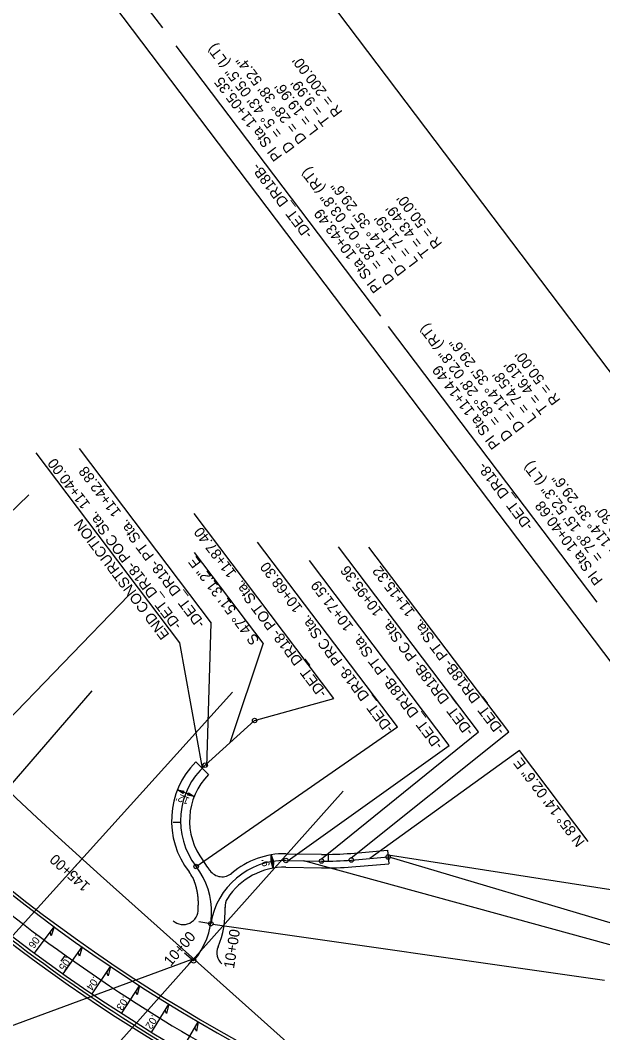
# Model space of a CAD drawing. Extents: x 473658 to 481584, y 489119 to 506230.
# Drawn here: x 476657 to 477047, y 500561 to 501237 of the extents above; entities that cross this region are included whole.
import ezdxf

# ---------------------------------------------------------------- set-up
doc = ezdxf.new("R2010")
doc.units = 0
for name, color, linetype in [('Exist Horizontal Alignment', 7, 'Continuous'), ('Prop Dimension', 7, 'Continuous'), ('Prop EOT', 7, 'Continuous'), ('Prop Grid Mask', 7, 'Continuous'), ('Prop Guardrail', 7, 'Continuous'), ('Prop Horizontal Alignment', 7, 'Continuous'), ('Prop Horizontal Alignment Curve and Spiral Data', 7, 'Continuous'), ('Prop Horizontal Alignment Direction Label', 7, 'Continuous'), ('Prop Horizontal Alignment Station Label', 7, 'Continuous'), ('Prop Horizontal Alignment Tick Label', 7, 'Continuous'), ('Prop Horizontal Alignment Tick Large', 7, 'Continuous'), ('Prop Horizontal Alignment Tick Small', 7, 'Continuous'), ('Prop Paved Shoulder', 7, 'Continuous'), ('Prop Superelevation  Arrow CELL', 7, 'Continuous'), ('Prop Superelevation Label', 7, 'Continuous'), ('Scratch_Level_6', 7, 'Continuous'), ('Sheet Plan And Profile CELL', 7, 'Continuous')]:
    doc.layers.add(name, color=color, linetype=linetype)

msp = doc.modelspace()

# ---------------------------------------------------------------- linework, layer by layer
at = {"layer": 'Exist Horizontal Alignment'}
for points in [[(476766.35, 500720.84), (476762.45, 500723.22), (476766.95, 500722.29), (476766.12, 500721.76)], [(476769.71, 500721.17), (476773.61, 500718.8), (476769.11, 500719.72), (476769.94, 500720.25)], [(476824.98, 500675.22), (476824.99, 500679.79), (476826.53, 500675.46), (476825.65, 500675.89)], [(476826.5, 500675.48), (476826.49, 500670.92), (476824.95, 500675.24), (476825.83, 500674.81)]]:
    msp.add_lwpolyline(points, close=True, dxfattribs=at)
at = {"layer": 'Prop Dimension'}
for p, q in [((476773.61, 500718.8), (476762.45, 500723.22)), ((476826.49, 500670.92), (476824.99, 500679.79))]:
    msp.add_line(p, q, dxfattribs=at)
at = {"layer": 'Prop EOT'}
for p, q in [((476774.61, 500741.87), (476783.16, 500733.45)), ((476834.99, 500680.55), (476858.76, 500680.15)), ((476878.25, 500680.8), (476902.84, 500682.85)), ((476902.84, 500682.85), (476903.59, 500673.88)), ((476834.84, 500671.55), (476858.61, 500671.15)), ((476879, 500671.83), (476903.59, 500673.88))]:
    msp.add_line(p, q, dxfattribs=at)
for centre, radius, start, end in [((477327.21, 501507.62), 1089, 218.24077, 241.8577), ((477327.21, 501507.62), 1111, 218.24077, 241.40091), ((476814.51, 500702.58), 56, 135.44556, 217.60879), ((476814.51, 500702.58), 44, 135.44556, 217.60879), ((476834.08, 500626.05), 54.5, 89.04778, 130.38858), ((476862.01, 500875.62), 195.5, 269.04778, 274.76596), ((476735.29, 500641.56), 56, 31.76656, 37.60879), ((476834.08, 500626.05), 45.5, 89.04778, 147.34296), ((476862.01, 500875.62), 204.5, 269.04778, 274.76596), ((476735.29, 500641.56), 44, 31.76656, 37.60879), ((476792.29, 500675.18), 10, 215.7109, 310.38858), ((476804.19, 500645.21), 10, 147.34296, 183.03589), ((476766.25, 500643.24), 10, 228.41849, 3.11379), ((476735.29, 500641.56), 59, 336.83919, 3.11867), ((476798.73, 500614.42), 10, 156.83919, 228.41849)]:
    msp.add_arc(centre, radius, start, end, dxfattribs=at)
msp.add_open_spline([(476784.35, 500669.1), (476784.32, 500669.13), (476784.3, 500669.17), (476784.27, 500669.2), (476784.2, 500669.31), (476784.12, 500669.41), (476784.05, 500669.51), (476783.97, 500669.62), (476783.9, 500669.72), (476783.82, 500669.82), (476783.75, 500669.92), (476783.67, 500670.03), (476783.6, 500670.13), (476783.52, 500670.23), (476783.44, 500670.33), (476783.37, 500670.43), (476783.21, 500670.63), (476783.06, 500670.84), (476782.9, 500671.04)], degree=3, dxfattribs=at)
msp.add_spline([(476776.23, 500643.78), (476776.26, 500644.06), (476776.28, 500644.34), (476776.3, 500644.62), (476776.32, 500644.9), (476776.33, 500645.18), (476776.35, 500645.46), (476776.36, 500645.74), (476776.37, 500646.03), (476776.38, 500646.31), (476776.39, 500646.59), (476776.39, 500646.87), (476776.4, 500647.16), (476776.4, 500647.44), (476776.4, 500647.72), (476776.4, 500648.01), (476776.39, 500648.29), (476776.39, 500648.58), (476776.38, 500648.86), (476776.37, 500649.15), (476776.35, 500649.43), (476776.34, 500649.72), (476776.32, 500650), (476776.3, 500650.29), (476776.28, 500650.57), (476776.26, 500650.86), (476776.24, 500651.14), (476776.21, 500651.43), (476776.18, 500651.72), (476776.15, 500652), (476776.12, 500652.29), (476776.09, 500652.58), (476776.05, 500652.86), (476776.01, 500653.15), (476775.97, 500653.43), (476775.93, 500653.72), (476775.88, 500654.01), (476775.84, 500654.29), (476775.79, 500654.58), (476775.74, 500654.87), (476775.69, 500655.15), (476775.63, 500655.44), (476775.58, 500655.72), (476775.52, 500656.01), (476775.46, 500656.29), (476775.39, 500656.58), (476775.33, 500656.86), (476775.26, 500657.15), (476775.19, 500657.43), (476775.12, 500657.72), (476775.05, 500658), (476774.98, 500658.29), (476774.9, 500658.57), (476774.82, 500658.85), (476774.74, 500659.14), (476774.66, 500659.42), (476774.57, 500659.7), (476774.49, 500659.99), (476774.4, 500660.27), (476774.31, 500660.55), (476774.21, 500660.83), (476774.12, 500661.11), (476774.02, 500661.39), (476773.92, 500661.67), (476773.82, 500661.95), (476773.72, 500662.23), (476773.61, 500662.51), (476773.51, 500662.79), (476773.4, 500663.06), (476773.29, 500663.34), (476773.17, 500663.62), (476773.06, 500663.89), (476772.94, 500664.17), (476772.7, 500664.72)], degree=3, dxfattribs=at)
at = {"layer": 'Prop Grid Mask'}
msp.add_lwpolyline([(477240.37, 500559.92), (476603.51, 501401.29), (476696.24, 501471.48), (477333.1, 500630.11)], close=True, dxfattribs=at)
at = {"layer": 'Prop Guardrail'}
msp.add_arc((477327.21, 501507.62), 1115, 218.24077, 239.00479, dxfattribs=at)
at = {"layer": 'Prop Horizontal Alignment'}
for p, q in [((476780.96, 500739.66), (476813.97, 500769.53)), ((476878.62, 500676.32), (476903.24, 500678.37)), ((476834.91, 500676.05), (476858.68, 500675.65)), ((477070.66, 500345.01), (476711.11, 500665.95))]:
    msp.add_line(p, q, dxfattribs=at)
for centre, radius, start, end in [((478615.62, 502799.59), 2860, 203.81642, 228.24762), ((477327.21, 501507.62), 1100, 218.24077, 241.8577), ((476814.51, 500702.58), 50, 132.14135, 217.60879), ((476735.29, 500641.56), 50, 319.34469, 37.60879), ((476834.08, 500626.05), 50, 89.04778, 171.08217), ((476862.01, 500875.62), 200, 269.04778, 274.76596)]:
    msp.add_arc(centre, radius, start, end, dxfattribs=at)
at = {"layer": 'Prop Horizontal Alignment Curve and Spiral Data'}
for p, q in [((476752.6, 501231.95), (476622.16, 501404.27)), ((476898.3, 501039.46), (476761.57, 501220.09)), ((477042.84, 500848.51), (476903.48, 501032.62))]:
    msp.add_line(p, q, dxfattribs=at)
at = {"layer": 'Prop Horizontal Alignment Station Label'}
for p, q in [((476667.82, 500948.24), (476763.86, 500821.36)), ((476696.65, 500951.06), (476784.89, 500834.49)), ((476866.97, 500784.27), (476773.53, 500907.7)), ((476909.36, 500765.2), (476815.93, 500888.64)), ((476819.78, 500821.18), (476773.92, 500881.77)), ((476963.51, 500761.95), (476870.07, 500885.38)), ((476983.76, 500761.85), (476890.33, 500885.29)), ((476944.01, 500752.85), (476850.57, 500876.28)), ((476781.97, 500738.54), (476784.89, 500834.49)), ((476763.86, 500821.36), (476778.88, 500737.66)), ((476819.78, 500821.18), (476797.47, 500754.59)), ((476813.97, 500769.53), (476866.97, 500784.27)), ((476774.9, 500672.07), (476909.36, 500765.2)), ((476858.71, 500677.15), (476963.51, 500761.95)), ((476878.5, 500677.81), (476983.76, 500761.85)), ((476836.41, 500676.02), (476944.01, 500752.85)), ((476991.06, 500749.39), (476890.93, 500677.34)), ((477036.92, 500688.8), (476991.06, 500749.39)), ((476903.12, 500679.86), (477119.45, 500646.11)), ((477089.88, 500622.89), (476903.22, 500678.37)), ((477068.24, 500615), (476846.8, 500675.85)), ((476786.17, 500633.57), (477047.84, 500596.21)), ((476772.09, 500609.96), (476453.22, 500492.62))]:
    msp.add_line(p, q, dxfattribs=at)
for centre in [(476813.97, 500769.53), (476780.96, 500739.66), (476834.91, 500676.05), (476834.91, 500676.05), (476858.68, 500675.65), (476858.68, 500675.65), (476878.62, 500676.32), (476878.62, 500676.32), (476903.24, 500678.37), (476903.24, 500678.37), (476774.9, 500672.07), (476784.69, 500633.8), (476784.69, 500633.8), (476773.22, 500608.98)]:
    msp.add_circle(centre, 1.5, dxfattribs=at)
at = {"layer": 'Prop Horizontal Alignment Tick Large'}
for p, q in [((476698.65, 500677.13), (476693.29, 500671.2)), ((476784.69, 500633.8), (476776.78, 500635.04)), ((476784.69, 500633.8), (476776.78, 500635.04)), ((476773.22, 500608.98), (476767.15, 500614.19))]:
    msp.add_line(p, q, dxfattribs=at)
at = {"layer": 'Prop Horizontal Alignment Tick Small'}
for p, q in [((476764.52, 500701.46), (476759.52, 500701.35)), ((476863.32, 500675.63), (476863.29, 500680.63)), ((476863.32, 500675.63), (476863.29, 500680.63)), ((476687.43, 500612.82), (476684.52, 500608.75)), ((476773.22, 500610.51), (476769.89, 500606.78))]:
    msp.add_line(p, q, dxfattribs=at)
at = {"layer": 'Prop Paved Shoulder'}
for radius, end in [(1087, 241.8577), (1113, 241.70868)]:
    msp.add_arc((477327.21, 501507.62), radius, 218.24077, end, dxfattribs=at)
at = {"layer": 'Prop Superelevation  Arrow CELL'}
for points in [[(476680.02, 500631.8), (476678.06, 500625.79), (476677.27, 500628.08)], [(476698.74, 500618.28), (476696.91, 500612.22), (476696.07, 500614.5)], [(476717.74, 500605.15), (476716.04, 500599.06), (476715.15, 500601.31)], [(476737.02, 500592.42), (476735.44, 500586.3), (476734.51, 500588.54)], [(476756.56, 500580.11), (476755.12, 500573.96), (476754.13, 500576.17)], [(476776.36, 500568.22), (476775.05, 500562.03), (476774.02, 500564.23)]]:
    msp.add_lwpolyline(points, close=True, dxfattribs=at)
at = {"layer": 'Prop Superelevation Label'}
for p, q in [((476666.94, 500614.11), (476680.02, 500631.8)), ((476686.04, 500600.31), (476698.74, 500618.28)), ((476705.43, 500586.91), (476717.74, 500605.15)), ((476725.09, 500573.94), (476737.02, 500592.42)), ((476745.2, 500561.65), (476756.56, 500580.11)), ((476765.23, 500549.24), (476776.36, 500568.22))]:
    msp.add_line(p, q, dxfattribs=at)
at = {"layer": 'Scratch_Level_6'}
msp.add_line((476509.12, 500562.51), (476705.47, 500789.34), dxfattribs=at)
at = {"layer": 'Sheet Plan And Profile CELL'}
for p, q in [((476446.96, 500712.24), (476663.1, 500920.29)), ((476521.25, 500637.71), (476729.99, 500853.18)), ((476598.11, 500565.82), (476799.19, 500788.45)), ((476673.33, 500498.6), (476873.11, 500722.41))]:
    msp.add_line(p, q, dxfattribs=at)

# ---------------------------------------------------------------- texts
at = {"layer": 'Prop Dimension'}
for s, rotation, p in [("12'", 158.37706, (476770.86, 500717.73)), ("9'", 99.60568, (476824.2, 500672.44))]:
    msp.add_text(s, height=5, rotation=rotation, dxfattribs=at).set_placement(p)
at = {"layer": 'Prop Horizontal Alignment Curve and Spiral Data'}
for s, p in [('= 5%%d 43\' 05.5" (LT)', (476833.11, 501161.81)), ('D = 28%%d 38\' 52.4"', (476849.08, 501157.78)), ("R = 200.00'", (476873, 501175.88)), ('PI Sta 11+05.35', (476832.72, 501146.24)), ("L = 19.96'", (476857.05, 501163.81)), ("T = 9.99'", (476865.02, 501169.85)), ('D', (476841.1, 501151.74)), ('= 82%%d 02\' 03.8" (RT)', (476899.72, 501073.81)), ('D = 114%%d 35\' 29.6"', (476915.69, 501069.78)), ("R = 50.00'", (476939.61, 501087.88)), ('PI Sta 10+43.49', (476899.33, 501058.24)), ("T = 43.49'", (476931.63, 501081.85)), ("L = 71.59'", (476923.66, 501075.81)), ('D', (476907.71, 501063.74)), ('= 85%%d 28\' 02.8" (RT)', (476978.77, 500969.38)), ('D = 114%%d 35\' 29.6"', (476994.73, 500965.35)), ("R = 50.00'", (477018.65, 500983.45)), ("T = 46.19'", (477010.68, 500977.42)), ('PI Sta 11+14.49', (476978.38, 500953.81)), ("L = 74.58'", (477002.71, 500971.38)), ('D', (476986.76, 500959.31)), ('= 78%%d 15\' 52.3" (LT)', (477047.39, 500878.72)), ('D = 114%%d 35\' 29.6"', (477063.36, 500874.69)), ('PI Sta 10+40.68', (477047, 500863.16)), ("L = 68.30'", (477071.33, 500880.73))]:
    msp.add_text(s, height=7, rotation=127.12364, dxfattribs=at).set_placement(p)
at = {"layer": 'Prop Horizontal Alignment Direction Label'}
for s, p in [('S 47%%d 51\' 31.2" E', (476817.45, 500823.19)), ('N 85%%d 14\' 02.6" E', (477034.99, 500688.49))]:
    msp.add_text(s, height=7, rotation=127.12364, dxfattribs=at).set_placement(p)
at = {"layer": 'Prop Horizontal Alignment Station Label'}
for s, rotation, p in [('-DET_DR18B-', 127.12364, (476853.15, 501094.34)), ('-DET_DR18- POC Sta.  11+40.00', 127.1612, (476765.73, 500833.18)), ('-DET_DR18-', 127.12364, (477000.63, 500899.5)), ('-DET_DR18- PT Sta.  11+42.88', 127.12364, (476781.36, 500834.4)), ('END CONSTRUCTION', 127.1612, (476757.36, 500826.83)), ('-DET_DR18- POT Sta.  11+87.40', 127.12364, (476862.77, 500788.01)), ('-DET_DR18- PRC Sta.  10+68.30', 127.12364, (476907.29, 500764.31)), ('-DET_DR18B- PC Sta.  10+95.36', 127.12364, (476960.68, 500762.33)), ('-DET_DR18B- PT Sta.  11+15.32', 127.12364, (476981.44, 500762.86)), ('-DET_DR18B- PT Sta.  10+71.59', 127.12364, (476940.27, 500753.17))]:
    msp.add_text(s, height=7, rotation=rotation, dxfattribs=at).set_placement(p)
at = {"layer": 'Prop Horizontal Alignment Tick Label'}
for s, rotation, p in [('145+00', 137.91226, (476704.44, 500659.78)), ('10+00', 81.08217, (476800.19, 500603.56)), ('10+00', 49.34469, (476757.92, 500604.98))]:
    msp.add_text(s, height=7, rotation=rotation, dxfattribs=at).set_placement(p)
at = {"layer": 'Prop Superelevation Label'}
for s, rotation, p in [('.06', 233.5372, (476667.95, 500627.17)), ('.05', 234.7524, (476688.13, 500612.36)), ('.04', 235.96759, (476706.42, 500599.09)), ('.03', 237.18278, (476726.31, 500585.86)), ('.02', 238.39797, (476745.67, 500573.41))]:
    msp.add_text(s, height=5, rotation=rotation, dxfattribs=at).set_placement(p)

doc.saveas('drawing.dxf')
